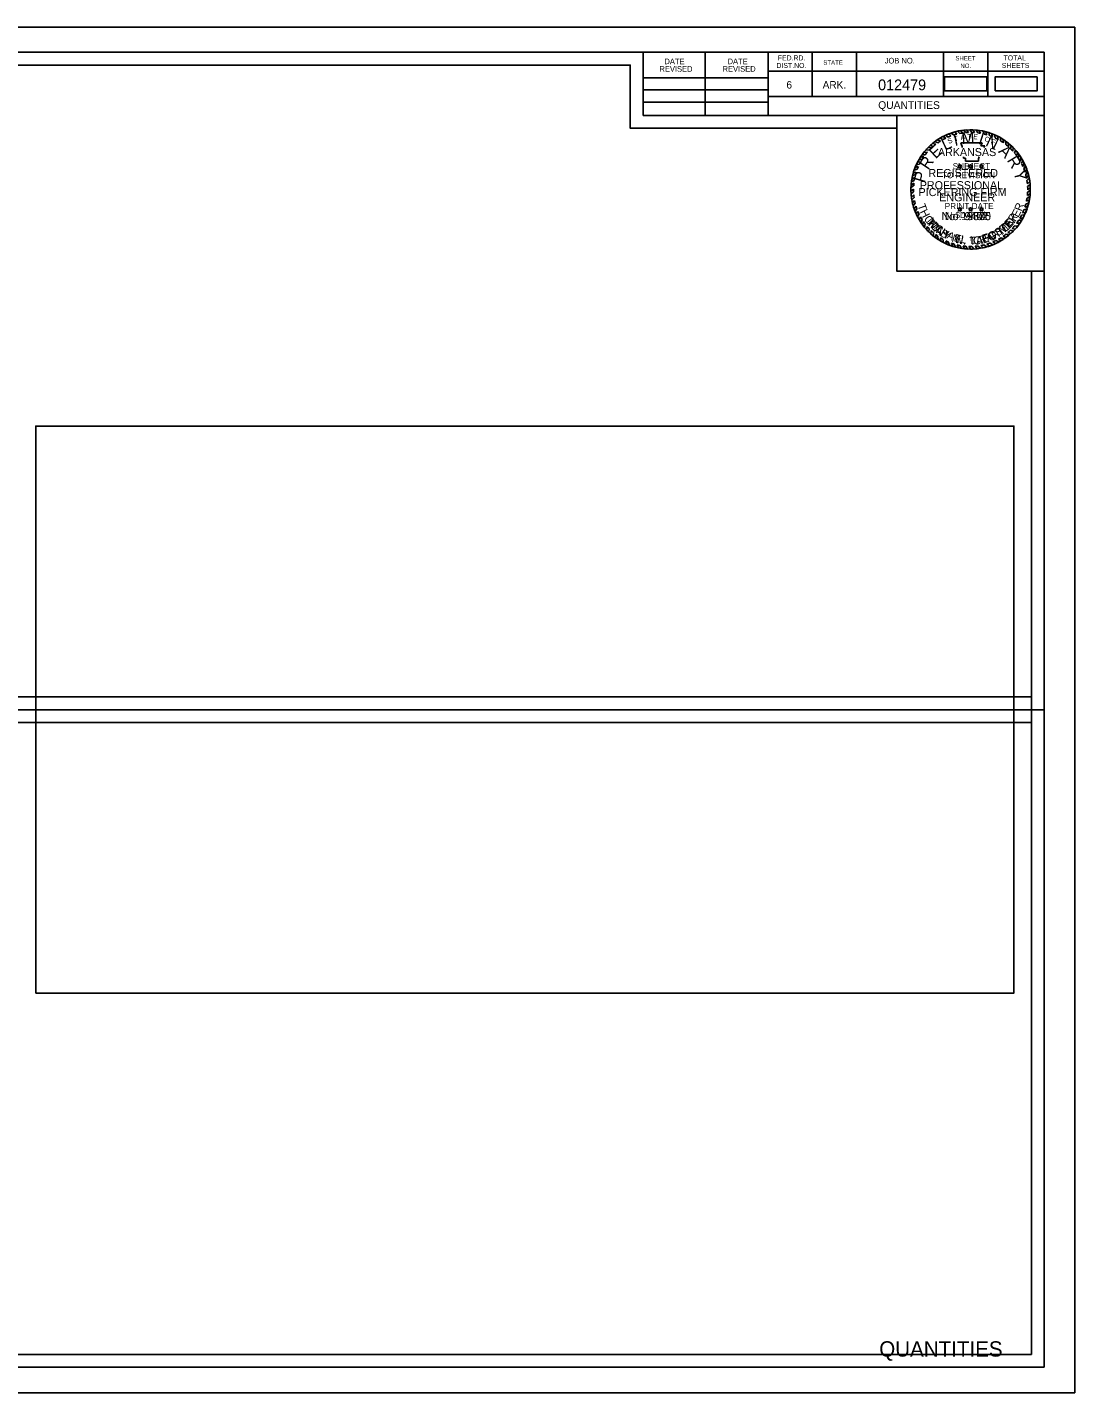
# Model space of a CAD drawing. Extents: x 1369290 to 1371547, y 379683 to 379897.
# Drawn here: x 1370921.3 to 1371084.9, y 379683.5 to 379896.8 of the extents above; entities that cross this region are included whole.
import ezdxf

# ---------------------------------------------------------------- set-up
doc = ezdxf.new("R2010")
doc.units = 0
for name, color, linetype in [('Default', 7, 'Continuous'), ('R_Border', 7, 'Continuous'), ('R_Border Notes', 7, 'Continuous'), ('R_Border Plan-Plan', 7, 'Continuous'), ('R_Border Title', 7, 'Continuous'), ('R_No Plot', 7, 'Continuous'), ('STAMP_PE_CRAFTON', 7, 'Continuous'), ('STAMP_PE_FOSTER', 7, 'Continuous'), ('STAMP_PE_SEAL-INFO', 7, 'Continuous'), ('STAMP_PE_TAEGTMEYER', 7, 'Continuous'), ('STAMP_PE_TXT', 7, 'Continuous'), ('STAMP_PRELIMINARY', 7, 'Continuous')]:
    doc.layers.add(name, color=color, linetype=linetype)

msp = doc.modelspace()

# ---------------------------------------------------------------- linework, layer by layer
at = {"layer": 'Default'}
for points in [[(1371064.59, 379886.89), (1371071.16, 379886.89), (1371071.16, 379889.08), (1371064.59, 379889.08)], [(1371072.46, 379886.89), (1371079.03, 379886.89), (1371079.03, 379889.08), (1371072.46, 379889.08)], [(1370922.66, 379745.92), (1371075.42, 379745.92), (1371075.42, 379834.51), (1370922.66, 379834.51)]]:
    msp.add_lwpolyline(points, close=True, dxfattribs=at)
at = {"layer": 'R_Border'}
for p, q in [((1370763.97, 379892.93), (1371080.15, 379892.93)), ((1371017.51, 379883.05), (1371017.51, 379892.93)), ((1371027.19, 379883.05), (1371027.19, 379892.93)), ((1371037.05, 379892.93), (1371037.05, 379883.05)), ((1371043.89, 379892.93), (1371043.89, 379885.99)), ((1371050.83, 379892.93), (1371050.83, 379885.99)), ((1371064.41, 379892.93), (1371064.41, 379885.99)), ((1371071.35, 379892.93), (1371071.35, 379885.99)), ((1371080.15, 379687.47), (1371080.15, 379892.93)), ((1371017.51, 379888.91), (1371037.05, 379888.91)), ((1371080.15, 379889.99), (1371037.05, 379889.99)), ((1371080.15, 379890.01), (1371080.15, 379890.01)), ((1371017.51, 379887.05), (1371037.05, 379887.05)), ((1371017.51, 379885.11), (1371037.05, 379885.11)), ((1371080.15, 379885.99), (1371037.05, 379885.99)), ((1371040.01, 379885.99), (1371080.15, 379885.99)), ((1371080.15, 379883.05), (1371017.51, 379883.05)), ((1371080.15, 379687.47), (1370763.97, 379687.47))]:
    msp.add_line(p, q, dxfattribs=at)
at = {"layer": 'R_Border Plan-Plan'}
msp.add_line((1370763.97, 379790.2), (1371080.15, 379790.2), dxfattribs=at)
at = {"layer": 'R_No Plot'}
for points in [[(1370751.56, 379896.82), (1371084.9, 379896.82), (1371084.9, 379683.48), (1370751.56, 379683.48)], [(1371078.15, 379792.2), (1370765.97, 379792.2), (1370765.97, 379890.93), (1371015.51, 379890.93), (1371015.51, 379881.05), (1371033.05, 379881.05), (1371057.15, 379881.05), (1371057.15, 379858.71), (1371078.15, 379858.71)], [(1370765.97, 379890.93), (1371015.51, 379890.93), (1371015.51, 379881.05), (1371033.05, 379881.05), (1371057.15, 379881.05), (1371057.15, 379858.71), (1371078.15, 379858.71), (1371078.15, 379689.47), (1370765.97, 379689.47)], [(1371057.15, 379883.05), (1371080.15, 379883.05), (1371080.15, 379858.71), (1371057.15, 379858.71)], [(1370765.97, 379788.2), (1371078.15, 379788.2), (1371078.15, 379689.47), (1370765.97, 379689.47)]]:
    msp.add_lwpolyline(points, close=True, dxfattribs=at)
at = {"layer": 'STAMP_PE_SEAL-INFO'}
for p, q in [((1371064.32, 379879.75), (1371064.78, 379879.52)), ((1371064.75, 379879.96), (1371065.14, 379879.68)), ((1371065.26, 379880.18), (1371065.55, 379879.85)), ((1371065.6, 379880.3), (1371065.99, 379880)), ((1371066.2, 379880.49), (1371066.48, 379880.14)), ((1371066.58, 379880.58), (1371066.94, 379880.24)), ((1371067.07, 379880.68), (1371067.37, 379880.31)), ((1371067.58, 379880.75), (1371067.86, 379880.37)), ((1371068.32, 379880.4), (1371068.01, 379880.79)), ((1371068.82, 379880.4), (1371068.54, 379880.81)), ((1371069.27, 379880.38), (1371069.01, 379880.81)), ((1371069.78, 379880.33), (1371069.49, 379880.77)), ((1371070.2, 379880.27), (1371069.95, 379880.72)), ((1371070.77, 379880.15), (1371070.59, 379880.61)), ((1371071.17, 379880.04), (1371071.01, 379880.51)), ((1371071.62, 379879.89), (1371071.48, 379880.37)), ((1371072.04, 379879.73), (1371071.89, 379880.23)), ((1371072.5, 379879.53), (1371072.4, 379880.02)), ((1371072.95, 379879.3), (1371072.86, 379879.81)), ((1371061.68, 379877.69), (1371062.21, 379877.65)), ((1371062.01, 379878.04), (1371062.55, 379877.99)), ((1371062.34, 379878.36), (1371062.8, 379878.22)), ((1371062.69, 379878.66), (1371063.22, 379878.56)), ((1371063.06, 379878.99), (1371063.52, 379878.78)), ((1371063.48, 379879.25), (1371063.93, 379879.05)), ((1371063.87, 379879.5), (1371064.3, 379879.27)), ((1371067.12, 379878.78), (1371070.46, 379878.78)), ((1371067.24, 379878.47), (1371067.12, 379878.78)), ((1371067.34, 379878.18), (1371067.24, 379878.47)), ((1371067.35, 379878.06), (1371067.34, 379878.18)), ((1371070.46, 379878.78), (1371070.24, 379878.29)), ((1371070.24, 379878.29), (1371070.87, 379878.29)), ((1371070.87, 379878.29), (1371070.73, 379878.06)), ((1371073.33, 379879.07), (1371073.29, 379879.57)), ((1371073.77, 379878.78), (1371073.74, 379879.3)), ((1371074.13, 379878.52), (1371074.16, 379879)), ((1371074.57, 379878.15), (1371074.59, 379878.67)), ((1371074.89, 379877.85), (1371074.96, 379878.35)), ((1371075.25, 379877.48), (1371075.31, 379878.01)), ((1371075.52, 379877.16), (1371075.66, 379877.63)), ((1371060.16, 379875.35), (1371060.66, 379875.46)), ((1371060.35, 379875.74), (1371060.85, 379875.81)), ((1371060.58, 379876.17), (1371061.07, 379876.19)), ((1371060.83, 379876.57), (1371061.34, 379876.6)), ((1371061.06, 379876.91), (1371061.57, 379876.91)), ((1371061.34, 379877.28), (1371061.89, 379877.3)), ((1371067.54, 379876.35), (1371067.52, 379876.57)), ((1371067.86, 379876.35), (1371067.54, 379876.35)), ((1371067.86, 379875.92), (1371067.86, 379876.35)), ((1371069.89, 379875.92), (1371067.86, 379875.92)), ((1371069.9, 379876.26), (1371069.89, 379875.92)), ((1371069.98, 379876.57), (1371069.9, 379876.26)), ((1371075.84, 379876.75), (1371075.98, 379877.25)), ((1371076.06, 379876.43), (1371076.24, 379876.89)), ((1371076.37, 379875.93), (1371076.55, 379876.42)), ((1371076.57, 379875.57), (1371076.8, 379876.01)), ((1371076.8, 379875.08), (1371077.03, 379875.57)), ((1371059.93, 379873.36), (1371059.46, 379873.11)), ((1371059.57, 379873.6), (1371060.04, 379873.8)), ((1371059.67, 379874.01), (1371060.15, 379874.18)), ((1371059.83, 379874.51), (1371060.31, 379874.65)), ((1371059.98, 379874.92), (1371060.48, 379875.07)), ((1371076.94, 379874.75), (1371077.21, 379875.18)), ((1371077.14, 379874.2), (1371077.41, 379874.67)), ((1371077.25, 379873.83), (1371077.54, 379874.28)), ((1371077.38, 379873.27), (1371077.7, 379873.72)), ((1371077.45, 379872.89), (1371077.8, 379873.25)), ((1371059.75, 379872.04), (1371059.33, 379871.78)), ((1371059.73, 379871.55), (1371059.33, 379871.21)), ((1371059.79, 379872.46), (1371059.35, 379872.18)), ((1371059.74, 379871.14), (1371059.35, 379870.81)), ((1371059.84, 379872.9), (1371059.4, 379872.68)), ((1371077.51, 379872.38), (1371077.89, 379872.72)), ((1371077.55, 379871.97), (1371077.94, 379872.26)), ((1371077.55, 379871.04), (1371077.97, 379871.32)), ((1371077.56, 379871.45), (1371077.96, 379871.77)), ((1371059.77, 379870.64), (1371059.4, 379870.29)), ((1371059.82, 379870.21), (1371059.47, 379869.84)), ((1371059.9, 379869.75), (1371059.56, 379869.39)), ((1371060, 379869.34), (1371059.68, 379868.92)), ((1371077.26, 379869.2), (1371077.73, 379869.4)), ((1371077.37, 379869.65), (1371077.82, 379869.84)), ((1371077.46, 379870.15), (1371077.9, 379870.37)), ((1371077.51, 379870.54), (1371077.94, 379870.79)), ((1371060.12, 379868.89), (1371059.83, 379868.47)), ((1371060.26, 379868.47), (1371059.98, 379868.05)), ((1371060.43, 379868.04), (1371060.17, 379867.62)), ((1371060.6, 379867.66), (1371060.37, 379867.19)), ((1371060.83, 379867.2), (1371060.64, 379866.71)), ((1371076.33, 379866.97), (1371076.83, 379867.03)), ((1371076.6, 379867.47), (1371077.09, 379867.54)), ((1371076.76, 379867.81), (1371077.25, 379867.9)), ((1371076.98, 379868.32), (1371077.46, 379868.45)), ((1371077.11, 379868.7), (1371077.6, 379868.9)), ((1371061.07, 379866.79), (1371060.89, 379866.32)), ((1371061.27, 379866.48), (1371061.16, 379865.93)), ((1371061.55, 379866.09), (1371061.45, 379865.56)), ((1371061.86, 379865.71), (1371061.77, 379865.19)), ((1371062.16, 379865.38), (1371062.1, 379864.85)), ((1371062.48, 379865.05), (1371062.45, 379864.52)), ((1371062.83, 379864.74), (1371062.82, 379864.21)), ((1371074.47, 379864.74), (1371074.94, 379864.61)), ((1371074.87, 379865.11), (1371075.31, 379864.97)), ((1371075.13, 379865.37), (1371075.6, 379865.29)), ((1371075.51, 379865.8), (1371075.97, 379865.73)), ((1371075.82, 379866.2), (1371076.32, 379866.2)), ((1371076.16, 379866.69), (1371076.64, 379866.69)), ((1371063.19, 379864.44), (1371063.2, 379863.92)), ((1371063.52, 379864.19), (1371063.56, 379863.68)), ((1371063.95, 379863.91), (1371064.01, 379863.4)), ((1371064.3, 379863.71), (1371064.39, 379863.19)), ((1371064.78, 379863.46), (1371064.94, 379862.94)), ((1371065.16, 379863.29), (1371065.33, 379862.78)), ((1371065.65, 379863.1), (1371065.86, 379862.59)), ((1371066.06, 379862.96), (1371066.28, 379862.47)), ((1371066.57, 379862.82), (1371066.78, 379862.36)), ((1371066.96, 379862.74), (1371067.21, 379862.28)), ((1371067.46, 379862.66), (1371067.7, 379862.21)), ((1371067.9, 379862.61), (1371068.17, 379862.18)), ((1371068.38, 379862.58), (1371068.69, 379862.17)), ((1371068.84, 379862.58), (1371069.19, 379862.18)), ((1371069.36, 379862.61), (1371069.69, 379862.23)), ((1371069.8, 379862.65), (1371070.17, 379862.29)), ((1371070.25, 379862.72), (1371070.63, 379862.38)), ((1371070.74, 379862.83), (1371071.12, 379862.5)), ((1371071.2, 379862.95), (1371071.61, 379862.65)), ((1371071.69, 379863.11), (1371072.13, 379862.84)), ((1371072.11, 379863.28), (1371072.53, 379863.02)), ((1371072.57, 379863.49), (1371073.05, 379863.28)), ((1371072.98, 379863.7), (1371073.39, 379863.47)), ((1371073.39, 379863.95), (1371073.84, 379863.75)), ((1371073.74, 379864.17), (1371074.17, 379863.98)), ((1371074.2, 379864.52), (1371074.66, 379864.37))]:
    msp.add_line(p, q, dxfattribs=at)
for radius, start, end in [(9.32, 117.6544, 120.8099), (9.32, 111.3124, 114.7026), (8.91, 110.3086, 113.1659), (9.32, 105.2339, 109.0352), (8.91, 104.0352, 107.3615), (9.32, 99.7525, 102.7765), (8.91, 98.258, 101.0329), (9.32, 93.9381, 96.5517), (8.91, 92.1102, 95.0367), (9.32, 87.7298, 90.6707), (8.91, 85.9628, 88.9097), (9.32, 81.9732, 84.8236), (8.91, 79.9264, 82.696), (9.32, 75.3125, 77.9426), (8.91, 73.5575, 76.2314), (9.32, 69.6061, 72.3058), (8.91, 67.6248, 70.504), (9.32, 63.1329, 66.2704), (9.32, 135.4021, 138.3031), (8.91, 133.1331, 136.2562), (9.32, 129.7326, 132.5376), (8.91, 127.5297, 130.9683), (9.32, 123.6199, 126.5906), (8.91, 121.9746, 125.11), (8.91, 115.6869, 119.1583), (8.91, 61.1558, 64.3784), (9.32, 56.9003, 60.0942), (8.91, 54.9238, 58.2702), (8.91, 48.3016, 52.0395), (9.32, 50.3492, 53.7159), (8.91, 42.2212, 45.5512), (9.32, 44.3405, 47.3929), (9.32, 38.1247, 41.2316), (9.32, 152.864, 155.5189), (9.32, 147.0072, 149.899), (8.91, 151.0315, 153.573), (9.32, 141.6056, 144.4486), (8.91, 145.0197, 148.2104), (8.91, 139.301, 142.5873), (8.91, 36.135, 39.5311), (8.91, 29.9032, 33.6645), (9.32, 31.9614, 35.4294), (8.91, 23.7732, 27.2211), (9.32, 25.9391, 29.0125), (9.32, 164.3068, 166.894), (9.32, 158.4077, 161.0701), (8.91, 167.9048, 170.9039), (8.91, 162.4331, 165.0013), (8.91, 156.3402, 159.2319), (8.91, 17.6802, 21.4251), (9.32, 19.9538, 23.3141), (8.91, 11.5444, 15.2364), (9.32, 13.8421, 17.4447), (9.32, 7.5852, 10.8621), (9.32, 175.7409, 178.2066), (9.32, 181.7251, 184.1626), (9.32, 170.0003, 172.6878), (8.91, 179.6454, 182.2633), (8.91, 173.73, 176.4734), (8.91, 5.7599, 9.0606), (8.91, 359.7329, 3.0639), (9.32, 1.7215, 4.7268), (9.32, 355.7156, 358.9569), (9.32, 187.4204, 190.1927), (9.32, 193.0369, 195.9973), (8.91, 185.4539, 188.234), (8.91, 191.2274, 193.9858), (8.91, 341.777, 345.0925), (8.91, 348.0778, 351.3435), (8.91, 353.8632, 357.1274), (9.32, 343.8925, 347.035), (9.32, 349.8305, 353.0885), (9.32, 198.8967, 201.6281), (8.91, 196.9675, 199.8353), (9.32, 204.5479, 207.4328), (8.91, 202.7761, 205.4791), (8.91, 208.7883, 211.7934), (8.91, 329.5549, 333.2076), (8.91, 335.6038, 339.1858), (9.32, 331.4037, 334.9332), (9.32, 337.3837, 340.9933), (9.32, 210.8636, 213.6571), (9.32, 216.6115, 219.491), (8.91, 214.1838, 217.2747), (9.32, 222.48, 225.3801), (8.91, 220.3909, 223.3056), (8.91, 226.2494, 229.2407), (8.91, 310.7744, 314.3161), (9.32, 312.4518, 315.6633), (8.91, 316.6531, 320.3711), (9.32, 318.2846, 321.8043), (8.91, 323.5851, 327.4407), (9.32, 325.4405, 328.9872), (9.32, 228.3665, 231.348), (8.91, 232.229, 234.9336), (9.32, 234.295, 236.9452), (8.91, 238.2223, 240.8353), (9.32, 240.1977, 242.8613), (8.91, 244.3204, 246.9486), (9.32, 246.576, 249.1558), (8.91, 250.3491, 253.1216), (9.32, 252.5967, 255.3252), (8.91, 256.505, 259.1192), (8.91, 262.3783, 265.2012), (8.91, 268.3215, 271.277), (8.91, 274.6157, 277.4486), (8.91, 280.3459, 283.5814), (8.91, 286.6423, 289.9783), (9.32, 288.5709, 291.9733), (8.91, 292.8745, 296.1185), (9.32, 294.6481, 298.2166), (8.91, 299.0768, 302.1724), (9.32, 300.621, 303.8703), (8.91, 304.823, 308.5143), (9.32, 306.3721, 310.208), (9.32, 258.4433, 261.1398), (9.32, 264.1978, 267.1009), (9.32, 270.2548, 273.3361), (9.32, 276.4239, 279.4357), (9.32, 282.3199, 285.3702)]:
    msp.add_arc((1371068.65, 379871.49), radius, start, end, dxfattribs=at)
at = {"layer": 'STAMP_PE_TXT'}
for p, q in [((1371066.87, 379875.21), (1371066.95, 379875.44)), ((1371066.95, 379875.44), (1371067.02, 379875.21)), ((1371068.57, 379875.21), (1371068.65, 379875.44)), ((1371068.65, 379875.44), (1371068.72, 379875.21)), ((1371070.27, 379875.21), (1371070.34, 379875.44)), ((1371070.34, 379875.44), (1371070.42, 379875.21)), ((1371066.82, 379875.06), (1371066.63, 379875.21)), ((1371066.63, 379875.21), (1371066.87, 379875.21)), ((1371066.75, 379874.83), (1371066.82, 379875.06)), ((1371066.95, 379874.97), (1371066.75, 379874.83)), ((1371067.15, 379874.83), (1371066.95, 379874.97)), ((1371067.02, 379875.21), (1371067.27, 379875.21)), ((1371067.27, 379875.21), (1371067.07, 379875.06)), ((1371067.07, 379875.06), (1371067.15, 379874.83)), ((1371068.52, 379875.06), (1371068.32, 379875.21)), ((1371068.32, 379875.21), (1371068.57, 379875.21)), ((1371068.45, 379874.83), (1371068.52, 379875.06)), ((1371068.65, 379874.97), (1371068.45, 379874.83)), ((1371068.84, 379874.83), (1371068.65, 379874.97)), ((1371068.72, 379875.21), (1371068.97, 379875.21)), ((1371068.97, 379875.21), (1371068.77, 379875.06)), ((1371068.77, 379875.06), (1371068.84, 379874.83)), ((1371070.22, 379875.06), (1371070.02, 379875.21)), ((1371070.02, 379875.21), (1371070.27, 379875.21)), ((1371070.15, 379874.83), (1371070.22, 379875.06)), ((1371070.34, 379874.97), (1371070.15, 379874.83)), ((1371070.54, 379874.83), (1371070.34, 379874.97)), ((1371070.42, 379875.21), (1371070.66, 379875.21)), ((1371070.66, 379875.21), (1371070.47, 379875.06)), ((1371070.47, 379875.06), (1371070.54, 379874.83)), ((1371066.82, 379868.35), (1371066.63, 379868.5)), ((1371066.63, 379868.5), (1371066.87, 379868.5)), ((1371066.75, 379868.12), (1371066.82, 379868.35)), ((1371066.95, 379868.27), (1371066.75, 379868.12)), ((1371066.87, 379868.5), (1371066.95, 379868.73)), ((1371066.95, 379868.73), (1371067.02, 379868.5)), ((1371067.15, 379868.12), (1371066.95, 379868.27)), ((1371067.02, 379868.5), (1371067.27, 379868.5)), ((1371067.27, 379868.5), (1371067.07, 379868.35)), ((1371067.07, 379868.35), (1371067.15, 379868.12)), ((1371068.52, 379868.35), (1371068.32, 379868.5)), ((1371068.32, 379868.5), (1371068.57, 379868.5)), ((1371068.45, 379868.12), (1371068.52, 379868.35)), ((1371068.65, 379868.27), (1371068.45, 379868.12)), ((1371068.57, 379868.5), (1371068.65, 379868.73)), ((1371068.65, 379868.73), (1371068.72, 379868.5)), ((1371068.84, 379868.12), (1371068.65, 379868.27)), ((1371068.72, 379868.5), (1371068.97, 379868.5)), ((1371068.97, 379868.5), (1371068.77, 379868.35)), ((1371068.77, 379868.35), (1371068.84, 379868.12)), ((1371070.22, 379868.35), (1371070.02, 379868.5)), ((1371070.02, 379868.5), (1371070.27, 379868.5)), ((1371070.15, 379868.12), (1371070.22, 379868.35)), ((1371070.34, 379868.27), (1371070.15, 379868.12)), ((1371070.27, 379868.5), (1371070.34, 379868.73)), ((1371070.34, 379868.73), (1371070.42, 379868.5)), ((1371070.54, 379868.12), (1371070.34, 379868.27)), ((1371070.42, 379868.5), (1371070.66, 379868.5)), ((1371070.66, 379868.5), (1371070.47, 379868.35)), ((1371070.47, 379868.35), (1371070.54, 379868.12))]:
    msp.add_line(p, q, dxfattribs=at)
at = {"layer": 'STAMP_PRELIMINARY'}
msp.add_circle((1371068.65, 379871.49), 9.32, dxfattribs=at)

# ---------------------------------------------------------------- texts
at = {"layer": 'R_Border'}
for s, height, p in [('FED.RD.', 0.782, (1371038.53, 379891.65)), ('TOTAL', 0.782, (1371073.79, 379891.65)), ('REVISED', 0.879, (1371020.06, 379889.88)), ('DATE', 0.879, (1371020.84, 379891.06)), ('REVISED', 0.879, (1371029.92, 379889.88)), ('DATE', 0.879, (1371030.7, 379891.06)), ('DIST.NO.', 0.782, (1371038.33, 379890.47)), ('STATE', 0.684, (1371045.65, 379890.97)), ('JOB NO.', 0.879, (1371055.23, 379891.17)), ('SHEET', 0.684, (1371066.27, 379891.65)), ('NO.', 0.684, (1371067.05, 379890.47)), ('SHEETS', 0.782, (1371073.51, 379890.47)), ('6', 1.17, (1371039.89, 379887.25)), ('ARK.', 1.172, (1371045.55, 379887.25))]:
    msp.add_text(s, height=height, dxfattribs=at).set_placement(p)
at = {"layer": 'R_Border Notes'}
for s, height, p in [('012479', 1.68, (1371054.2, 379886.99)), ('QUANTITIES', 1.2, (1371054.22, 379884.07))]:
    msp.add_text(s, height=height, dxfattribs=at).set_placement(p)
at = {"layer": 'R_Border Title'}
msp.add_text('QUANTITIES', height=2.4, dxfattribs=at).set_placement((1371054.38, 379689.12))
at = {"layer": 'STAMP_PE_CRAFTON'}
for s, rotation, p in [('T', 310.7442, (1371061.61, 379866.39)), ('N', 49.2411, (1371074.93, 379865.51)), ('O', 317.6422, (1371062.28, 379865.58)), ('N', 324.4537, (1371063.12, 379864.79)), ('Y', 331.1686, (1371064.16, 379864.08)), ('F', 28.7821, (1371072.31, 379863.62)), ('T', 34.1136, (1371073.22, 379864.13)), ('O', 41.8391, (1371074.08, 379864.73)), ('N', 347.4752, (1371066.21, 379863.16)), ('.', 356.8926, (1371067.44, 379862.88)), ('C', 6.0117, (1371069.12, 379862.83)), ('R', 14.8189, (1371070.21, 379862.95)), ('A', 20.5125, (1371071.33, 379863.25))]:
    msp.add_text(s, height=1.25, rotation=rotation, dxfattribs=at).set_placement(p)
msp.add_text('No. 12370', height=1.25, dxfattribs=at).set_placement((1371064.11, 379866.69))
at = {"layer": 'STAMP_PE_FOSTER'}
for s, rotation, p in [('M', 308.339, (1371061.76, 379866.51)), ('E', 46.9613, (1371074.65, 379865.48)), ('R', 54.5031, (1371075.37, 379866.3)), ('I', 314.1842, (1371062.56, 379865.57)), ('C', 319.8733, (1371062.91, 379865.22)), ('H', 327.7235, (1371063.84, 379864.48)), ('A', 335.7276, (1371064.82, 379863.9)), ('O', 23.719, (1371071.72, 379863.57)), ('S', 31.7234, (1371072.84, 379864.1)), ('T', 39.4194, (1371073.79, 379864.73)), ('E', 343.5779, (1371065.96, 379863.43)), ('L', 350.8115, (1371067.02, 379863.16)), ('L', 1.2666, (1371068.56, 379863)), ('.', 6.8035, (1371069.61, 379863.06)), ('F', 15.8691, (1371070.68, 379863.24))]:
    msp.add_text(s, height=1.2, rotation=rotation, dxfattribs=at).set_placement(p)
msp.add_text('No. 9402', height=1.25, dxfattribs=at).set_placement((1371064.63, 379866.69))
at = {"layer": 'STAMP_PE_TAEGTMEYER'}
for s, rotation, p in [('T', 289.646, (1371060.34, 379869)), ('R', 69.57, (1371076.59, 379868)), ('H', 296.7339, (1371060.7, 379868.02)), ('O', 303.7708, (1371061.29, 379866.91)), ('E', 46.8094, (1371074.68, 379865.27)), ('Y', 53.9986, (1371075.42, 379866.08)), ('E', 63.0984, (1371076.09, 379867.02)), ('M', 314.2033, (1371061.95, 379865.96)), ('A', 321.0594, (1371062.91, 379864.99)), ('S', 327.8239, (1371063.74, 379864.35)), ('G', 23.3052, (1371071.65, 379863.35)), ('T', 31.466, (1371072.75, 379863.84)), ('M', 39.3, (1371073.64, 379864.39)), ('N', 344.2727, (1371065.63, 379863.34)), ('.', 350.6464, (1371066.84, 379863.01)), ('T', 3.0061, (1371068.51, 379862.81)), ('A', 8.9826, (1371069.56, 379862.87)), ('E', 17.6836, (1371070.6, 379863.02))]:
    msp.add_text(s, height=1.25, rotation=rotation, dxfattribs=at).set_placement(p)
msp.add_text('No. 19605', height=1.25, dxfattribs=at).set_placement((1371064.11, 379866.69))
at = {"layer": 'STAMP_PE_TXT'}
for s, rotation, p in [('T', 16.311, (1371066.17, 379878.97)), ('A', 9.0679, (1371067.13, 379879.22)), ('T', 1.8248, (1371068.12, 379879.35)), ('E', 355.2002, (1371069.03, 379879.36)), ('O', 342.2506, (1371070.75, 379879.08)), ('S', 23.5541, (1371065.24, 379878.59)), ('F', 335.0075, (1371071.72, 379878.74))]:
    msp.add_text(s, height=0.781, rotation=rotation, dxfattribs=at).set_placement(p)
for s, p in [('ARKANSAS', (1371063.54, 379876.7)), ('REGISTERED', (1371062.06, 379873.43)), ('PROFESSIONAL', (1371060.71, 379871.53)), ('ENGINEER', (1371063.75, 379869.63))]:
    msp.add_text(s, height=1.25, dxfattribs=at).set_placement(p)
at = {"layer": 'STAMP_PRELIMINARY'}
for s, rotation, p in [('I', 12.5248, (1371066.18, 379878.28)), ('M', 3.1074, (1371067.28, 379878.59)), ('I', 342.3164, (1371069.75, 379878.65)), ('N', 333.9382, (1371070.86, 379878.38)), ('E', 42.3578, (1371063.17, 379876.19)), ('L', 25.513, (1371064.65, 379877.52)), ('A', 315.6579, (1371072.89, 379877.35)), ('R', 56.2292, (1371062.02, 379874.45)), ('R', 301.3831, (1371074.26, 379876.04)), ('P', 73.913, (1371061.47, 379872.43)), ('Y', 283.2593, (1371075.35, 379874.25))]:
    msp.add_text(s, height=1.8, rotation=rotation, dxfattribs=at).set_placement(p)
for s, height, p in [('SUBJECT', 0.96, (1371065.85, 379874.64)), ('TO REVISION', 0.96, (1371064.18, 379873.25)), ('PICKERING FIRM', 1.25, (1371060.52, 379870.45)), ('PRINT DATE', 0.96, (1371064.6, 379868.41)), ('$DATE$', 0.96, (1371066.28, 379867.02))]:
    msp.add_text(s, height=height, dxfattribs=at).set_placement(p)

doc.saveas('drawing.dxf')
